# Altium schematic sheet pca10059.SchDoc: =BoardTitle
size A4; Organization: Nordic Semiconductor; SheetNumber: 1; SheetTotal: 1; CompanyName: Nordic Semiconductor; DocumentSize: A4
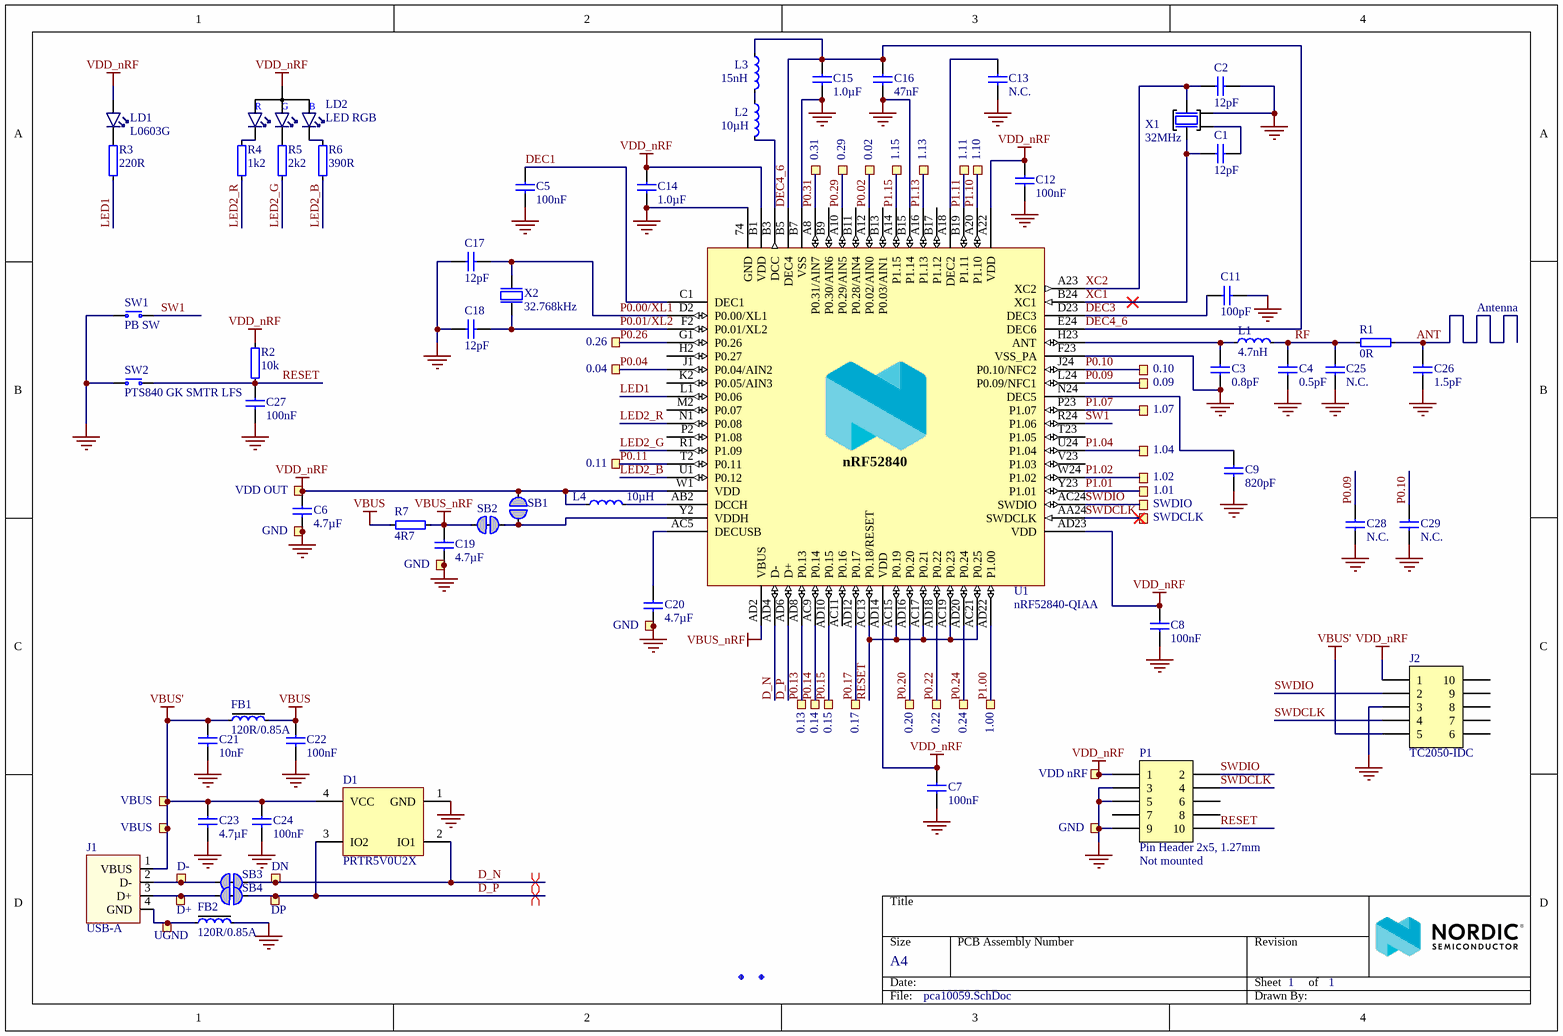
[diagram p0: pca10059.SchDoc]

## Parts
0.02  CH  [Castellated_Hole_0.9mm]  (value not drawn)  (no BOM)
0.04  Ø1.0mm,SMD  [TP_SMD_D1.0mm]  (value not drawn)  (no BOM)
0.09  CH  [Castellated_Hole_0.9mm]  (value not drawn)  (no BOM)
0.10  CH  [Castellated_Hole_0.9mm]  (value not drawn)  (no BOM)
0.11  Ø1.0mm,SMD  [TP_SMD_D1.0mm]  (value not drawn)  (no BOM)
0.13  CH  [Castellated_Hole_0.9mm]  (value not drawn)  (no BOM)
0.14  Ø1.0mm,SMD  [TP_SMD_D1.0mm]  (value not drawn)  (no BOM)
0.15  CH  [Castellated_Hole_0.9mm]  (value not drawn)  (no BOM)
0.17  CH  [Castellated_Hole_0.9mm]  (value not drawn)  (no BOM)
0.20  CH  [Castellated_Hole_0.9mm]  (value not drawn)  (no BOM)
0.22  CH  [Castellated_Hole_0.9mm]  (value not drawn)  (no BOM)
0.24  CH  [Castellated_Hole_0.9mm]  (value not drawn)  (no BOM)
0.26  Ø1.0mm,SMD  [TP_SMD_D1.0mm]  (value not drawn)  (no BOM)
0.29  CH  [Castellated_Hole_0.9mm]  (value not drawn)  (no BOM)
0.31  CH  [Castellated_Hole_0.9mm]  (value not drawn)  (no BOM)
1.00  CH  [Castellated_Hole_0.9mm]  (value not drawn)  (no BOM)
1.01  Ø1.0mm,SMD  [TP_SMD_D1.0mm]  (value not drawn)  (no BOM)
1.02  Ø1.0mm,SMD  [TP_SMD_D1.0mm]  (value not drawn)  (no BOM)
1.04  Ø1.0mm,SMD  [TP_SMD_D1.0mm]  (value not drawn)  (no BOM)
1.07  Ø1.0mm,SMD  [TP_SMD_D1.0mm]  (value not drawn)  (no BOM)
1.10  CH  [Castellated_Hole_0.9mm]  (value not drawn)  (no BOM)
1.11  Ø1.0mm,SMD  [TP_SMD_D1.0mm]  (value not drawn)  (no BOM)
1.13  CH  [Castellated_Hole_0.9mm]  (value not drawn)  (no BOM)
1.15  CH  [Castellated_Hole_0.9mm]  (value not drawn)  (no BOM)
C1  12pF  [CAPC0603X03L_C]
C2  12pF  [CAPC0603X03L_C]
C3  0.8pF  [CAPC0603X03L_C]
C4  0.5pF  [CAPC0603X03L_C]
C5  100nF  [CAPC0603X03L_C]
C6  4.7µF  [CAPC1608X06L]
C7  100nF  [CAPC0603X03L_C]
C8  100nF  [CAPC0603X03L_C]
C9  820pF  [CAPC0603X03L_C]
C11  100pF  [CAPC0603X03L_C]
C12  100nF  [CAPC0603X03L_C]
C13  N.C.  [CAPC0603X03L_C_NC]
C14  1.0µF  [CAPC1608X06L]
C15  1.0µF  [CAPC1608X06L]
C16  47nF  [CAPC0603X03L_C]
C17  12pF  [CAPC0603X03L_C]
C18  12pF  [CAPC0603X03L_C]
C19  4.7µF  [CAPC1005X04L]
C20  4.7µF  [CAPC1608X06L]
C21  10nF  [CAPC0603X03L_C]
C22  100nF  [CAPC0603X03L_C]
C23  4.7µF  [CAPC1005X04L]
C24  100nF  [CAPC0603X03L_C]
C25  N.C.  [CAPC0603X03L_C_NC]
C26  1.5pF  [CAPC0603X03L_C]
C27  100nF  [CAPC0603X03L_C]
C28  N.C.  [CAPC1005X04L_NC]
C29  N.C.  [CAPC1005X04L_NC]
D1  PRTR5V0U2X  [SOT190P230X110-4L]
D+  Ø1.0mm,SMD  [TP_SMD_D1.0mm]  (value not drawn)  (no BOM)
D-  Ø1.0mm,SMD  [TP_SMD_D1.0mm]  (value not drawn)  (no BOM)
DN  Ø1.0mm,SMD  [TP_SMD_D1.0mm]  (value not drawn)  (no BOM)
DP  Ø1.0mm,SMD  [TP_SMD_D1.0mm]  (value not drawn)  (no BOM)
FB1  120R/0.85A  [INDC0603X03L_C]
FB2  120R/0.85A  [INDC0603X03L_C]
Fid1  Fiducial mark  [Fiducial_Square]  (value not drawn)
Fid2  Fiducial mark  [Fiducial]  (value not drawn)
GND1  GND  [Castellated_Hole_0.9mm]  (no BOM)
GND2  GND  [Castellated_Hole_0.9mm_S]  (no BOM)
GND3  GND  [Castellated_Hole_0.9mm_S]  (no BOM)
GND4  GND  [TP_SMD_D1.0mm]  (no BOM)
J1  USB-A  [USB-A-PCB]  (no BOM)
J2  TC2050-IDC  [TC2050-IDC-NLFP]  (no BOM)
L1  4.7nH  [INDC0603X03L_C]
L2  10µH  [INDC1608X06L]
L3  15nH  [INDC1005X04L]
L4  10µH  [INDC1608X06L]
LD1  L0603G  [LED_0603_G]
LD2  LED RGB  [LED_RGB_0603]
P1  Pin Header 2x5, 1.27mm  Assembly: Not mounted  [HDR_2x5-SMD-1.27mm-NC]
R1  0R  [RESC0603X03L_C]
R2  10k  [RESC0603X03L_C]
R3  220R  [RESC0603X03L_C]
R4  1k2  [RESC0603X03L_C]
R5  2k2  [RESC0603X03L_C]
R6  390R  [RESC0603X03L_C]
R7  4R7  [RESC0603X03L_C]
SB1  Solderbridge  [Solderbridge]  (value not drawn)  (no BOM)
SB2  Solderbridge  [Solderbridge_Shorted]  (value not drawn)  (net tie, no BOM)
SB3  Solderbridge  [Solderbridge_Shorted]  (value not drawn)  (net tie, no BOM)
SB4  Solderbridge  [Solderbridge_Shorted]  (value not drawn)  (net tie, no BOM)
SW1  PB SW  [C&K_PTS810]
SW2  PTS840 GK SMTR LFS  [EVQP7A_J_B_K]
SWDCLK  CH  [Castellated_Hole_0.9mm_D]  (value not drawn)  (no BOM)
SWDIO  CH  [Castellated_Hole_0.9mm_D]  (value not drawn)  (no BOM)
U1  nRF52840-QIAA  [AQFN50P700X700X85_HS-74N]
UGND  Ø1.0mm,SMD  [TP_SMD_D1.0mm]  (value not drawn)  (no BOM)
VBUS1  VBUS  [Castellated_Hole_0.9mm]  (no BOM)
VBUS2  VBUS  [TP_SMD_D1.0mm]  (no BOM)
VDD_nRF  Ø1.0mm,SMD  [TP_SMD_D1.0mm]  (value not drawn)  (no BOM)
VDD_OUT  CH  [Castellated_Hole_0.9mm]  (value not drawn)  (no BOM)
X1  32MHz  [BT-XTAL_2016]
X2  32.768kHz  [XTAL_2012]

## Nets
GND: C2.2 C3.1 C4.1 C5.2 C6.2 C7.2 C8.2 C9.2 C11.2 C12.2 C13.2 C14.2 C15.1 C16.2 C17.2 C18.2 C19.2 C20.2 C21.1 C22.1 C23.1 C24.1 C25.2 C26.1 C27.1 C28.1 C29.2 D1.1(GND) FB2.2 GND1.1 GND2.1 GND3.1 GND4.1 J2.3 P1.3 P1.5 P1.9 SW1.2(COM) SW2.2(COM) U1.74(GND) U1.B7(VSS) U1.B15(P1.14) U1.F23(VSS_PA) X1.2(GND)
VBUS: C22.2 FB1.2 R7.2
VBUS': C21.2 C23.2 C24.2 D1.4(VCC) FB1.1 J1.1(VBUS) J2.5 VBUS1.1 VBUS2.1
VBUS_nRF: C19.1 R7.1 SB2.2 U1.AD2(VBUS)
VDD_nRF: C6.1 C7.1 C8.1 C12.1 C14.1 J2.1 L4.1 LD1.2(A) LD2.4(A) P1.1 R2.2 SB1.1 U1.A22(VDD) U1.AD14(VDD) U1.AD23(VDD) U1.B1(VDD) U1.W1(VDD) VDD_nRF.1 VDD_OUT.1
ANT: C26.2 R1.2
D_N: D1.2(IO1) DN.1 SB3.1 U1.AD4(D-)
D_P: D1.3(IO2) DP.1 SB4.1 U1.AD6(D+)
DEC1: C5.1 U1.C1(DEC1)
DEC3: C11.1 U1.D23(DEC3)
DEC4_6: C15.2 C16.1 L3.1 U1.B5(DEC4) U1.E24(DEC6)
LED1: R3.1 U1.L1(P0.06)
LED2_B: R6.1 U1.U1(P0.12)
LED2_G: R5.1 U1.R1(P1.09)
LED2_R: R4.1 U1.N1(P0.08)
P0.00/XL1: C17.1 U1.D2(P0.00/XL1) X2.1(inp)
P0.01/XL2: C18.1 U1.F2(P0.01/XL2) X2.2(out)
P0.02: 0.02.1 U1.A12(P0.02/AIN0)
P0.04: 0.04.1 U1.J1(P0.04/AIN2)
P0.09: 0.09.1 C28.2 U1.L24(P0.09/NFC1)
P0.10: 0.10.1 C29.1 U1.J24(P0.10/NFC2)
P0.11: 0.11.1 U1.T2(P0.11)
P0.13: 0.13.1 U1.AD8(P0.13)
P0.14: 0.14.1 U1.AC9(P0.14)
P0.15: 0.15.1 U1.AD10(P0.15)
P0.17: 0.17.1 U1.AD12(P0.17)
P0.20: 0.20.1 U1.AD16(P0.20)
P0.22: 0.22.1 U1.AD18(P0.22)
P0.24: 0.24.1 U1.AD20(P0.24)
P0.26: 0.26.1 U1.G1(P0.26)
P0.29: 0.29.1 U1.A10(P0.29/AIN5)
P0.31: 0.31.1 U1.A8(P0.31/AIN7)
P1.00: 1.00.1 U1.AD22(P1.00)
P1.01: 1.01.1 U1.Y23(P1.01)
P1.02: 1.02.1 U1.W24(P1.02)
P1.04: 1.04.1 U1.U24(P1.04)
P1.07: 1.07.1 U1.P23(P1.07)
P1.10: 1.10.1 U1.A20(P1.10)
P1.11: 1.11.1 U1.B19(P1.11)
P1.13: 1.13.1 U1.A16(P1.13)
P1.15: 1.15.1 U1.A14(P1.15)
RESET: C27.2 P1.10 R2.1 SW2.1(N.O) U1.AC13(P0.18/RESET) U1.AC15(P0.19) U1.AC17(P0.21) U1.AC19(P0.23) U1.AC21(P0.25)
RF: C4.2 C25.1 L1.2 R1.1
SW1: SW1.1(N.O) U1.R24(P1.06)
SWDCLK: J2.4 P1.4 SWDCLK.1 U1.AA24(SWDCLK)
SWDIO: J2.2 P1.2 SWDIO.1 U1.AC24(SWDIO)
XC1: C1.1 U1.B24(XC1) X1.1(IN)
XC2: C2.1 U1.A23(XC2) X1.3(OUT)
NetC1_2: C1.2 X1.4(GND)
NetC3_2: C3.2 L1.1 U1.H23(ANT)
NetC9_1: C9.1 U1.N24(DEC5)
NetC13_1: C13.1 U1.A18(DEC2)
NetC20_1: C20.1 U1.AC5(DECUSB)
NetD+_1: D+.1 J1.3(D+) SB4.2
NetD-_1: D-.1 J1.2(D-) SB3.2
NetFB2_1: FB2.1 J1.4(GND) UGND.1
NetL2_1: L2.1 L3.2
NetL2_2: L2.2 U1.B3(DCC)
NetL4_2: L4.2 U1.AB2(DCCH)
NetLD1_1: LD1.1(C) R3.2
NetLD2_1: LD2.1(C_RED) R4.2
NetLD2_2: LD2.2(C_GREEN) R5.2
NetLD2_3: LD2.3(C_BLUE) R6.2
NetSB1_2: SB1.2 SB2.1 U1.Y2(VDDH)

Not connected (* = marked no-connect by the designer): J2 6 7 8 9 10; P1 6 7 8; U1 AC11(P0.16) B9(P0.30/AIN6) B11(P0.28/AIN4) B13(P0.03/AIN1) B17(P1.12) H2(P0.27) K2(P0.05/AIN3) M2(P0.07) P2(P1.08) T23(P1.05) V23(P1.03)

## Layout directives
differential pair: D_N, D_P

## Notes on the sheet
- Antenna

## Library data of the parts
0.02 0.09 0.10 0.13 0.15 0.17 0.20 0.22 0.24 0.29 0.31 1.00 1.10 1.13 1.15 GND1 VBUS1 VDD_OUT = Castellated Hole 0.9mm: Manufacturer: N.A.; Pad Count: 1
0.04 0.11 0.14 0.26 1.01 1.02 1.04 1.07 1.11 D+ D- DN DP GND4 UGND VBUS2 VDD_nRF = TP_SMD_Ø1.0MM: 1.0mm circular SMD testpad; Manufacturer: Nordic Semiconductor; Manufacturer Part Number: N.A.; Pad Count: 1
C1 C2 C17 C18 = C0201-12p: Capacitor, NP0, ±2%; Manufacturer: N.A.; Part number IPS: 00000007848; Note: 25V; Pad Count: 2
C3 = C0201-0.8p: Capacitor, NP0, ±0.05pF, 50V; Manufacturer: Murata; Manufacturer Part Number: GJM0335C1HR80WB01; Part number IPS: 80000001975; Artikkelnr Noca: N.A.; Pad Count: 2
C4 = C0201-0.5p: Capacitor, NP0, ±0.05pF; Manufacturer: N.A.; Note: 50V; Pad Count: 2
C5 C7 C8 C12 C22 C24 C27 = C0201-100n: Capacitor, X5R, ±10%; Manufacturer: N.A.; Part number IPS: 00000001248, 00000002505; Note: 16V; Pad Count: 2
C6 C20 = C0603-4µ7: Capacitor, X5R, ±10%; Manufacturer: N.A.; Part number IPS: 00000007783; Note: 6.3V; Artikkelnr Noca: 20069060; Pad Count: 2
C9 = C0201-820p: Capacitor, X7R, ±10%; Manufacturer: N.A.; Part number IPS: 00000001249; Note: 25V; Pad Count: 2
C11 = C0201-100p: Capacitor, NP0, ±2%, 25V; Manufacturer: Murata; Manufacturer Part Number: GRM0335C1E101GA01; Part number IPS: 00000007853; Artikkelnr Noca: N.A.; Pad Count: 2
C13 C25 = C0201-N.C.: Not mounted; Manufacturer: N.A.; Note: Chip Cap; Assembly: Not mounted; Pad Count: 2
C14 C15 = C0603-1µ0: Capacitor, X7R, ±10%; Manufacturer: N.A.; Part number IPS: 00000000616; Note: 16V; Artikkelnr Noca: 20039282; Pad Count: 2
C16 = C0201-47n: Capacitor, X5R, ±10%; Manufacturer: N.A.; Part number IPS: 00000001250; Note: 10V; Pad Count: 2
C19 C23 = C0402-4µ7: Capacitor, X5R, ±20%; Manufacturer: N.A.; Part number IPS: 00000001251, 00000007165; Note: 10V; Artikkelnr Noca: 20039482; Pad Count: 2
C21 = C0201-10n: Capacitor, X7R, ±10%; Manufacturer: N.A.; Part number IPS: 00000003480; Note: 10V; Pad Count: 2
C26 = C0201-1.5p: Capacitor, NP0, ±0.1pF; Manufacturer: N.A.; Part number IPS: 00000007107; Note: 50V; Pad Count: 2
C28 C29 = C0402-N.C.: Not mounted; Manufacturer: N.A.; Assembly: Not mounted; Note: Chip Cap; Pad Count: 2
D1 = PRTR5V0U2X: Ultra low capacitance double rail-to-rail ESD protection diode; Manufacturer: NXP Semiconductors; Part number IPS: 00000009951; Note: N.A.; Artikkelnr Noca: 10069015; Pad Count: 4
FB1 FB2 = FB0201-120R@100M-850mA: Ferrite Bead, 120 Ohm @ 100MHz, 850mA, 150 mOhm Max; Manufacturer: Taiyo Yuden; Manufacturer Part Number: BKP0603HS121-T; Part number IPS: 00000001252; Note: Chip EMIFIL Inductor Type Chip Ferrite Bead; Artikkelnr Noca: N.A.; Pad Count: 2
Fid1 = Fid-Mark-Square: Manufacturer: N.A.; Value: N.A.; Pad Count: 1
Fid2 = Fid-Mark: Manufacturer: N.A.; Value: N.A.; Pad Count: 1
GND2 GND3 = Castellated Hole 0.9mm_S: Castellated Hole 0.9mm; Manufacturer: N.A.; Pad Count: 1
J1 = USB-A-PCB: USB-A PCB footprint; Manufacturer: N.A.; Pad Count: 4
J2 = TC2050-IDC-NLFP: CBL PLUG-OF-NAILS 10-PIN; Manufacturer: Tag-Connect LLC; Artikkelnr Noca: N.A.; Pad Count: 10
L1 = L0201-4n7: Inductor, 350mA, ±3%; Manufacturer: Murata; Manufacturer Part Number: LQP03TN4N7H02D; Part number IPS: 00000001792; Note: N.A.; Pad Count: 2
L2 L4 = L0603-10µ: Inductor, 80mA, ±10%; Manufacturer: Taiyo Yuden; Manufacturer Part Number: LBMF1608T100K; Part number IPS: 00000007794; Part number Norautron: N.A.; Note: LBMF1608T100K 10µH 80mA 0603; Artikkelnr Noca: 33029314; Pad Count: 2
L3 = L0402-15n: Inductor, 320mA, ±5%; Manufacturer: Taiyo Yuden; Manufacturer Part Number: HK100515NJ-T; Part number IPS: 00000001262; Part number Norautron: N.A.; Note: High frequency chip inductor ±10%; Artikkelnr Noca: 33029323; Pad Count: 2
LD1 = VS 25C7M5: LED, Green, 0603, 573nm, Vf=2.0V, 24mcd, - 40 to +85°C; Manufacturer: Victory Electronics; Part number IPS: 00000001274, 00000009961; Note: N.A.; Artikkelnr Noca: 13019193; Pad Count: 2
LD2 = APHF1608LSEEQBDZGKC: RGB LED 1.60 mm x 0.80 mm SMD; Manufacturer: Kingbright Company LLC; Part number IPS: 00000001254; Note: N.A.; Pad Count: 4
P1 = Pin Header 2x5 SMD, 1.27mm, KS, N.C.: Pin Header 2x5, 1.27mm (50mil), SMD, Keying Shroud; Manufacturer: W-CON; Manufacturer Part Number: 3132-10MS0BK00R1; Note: N.A.; Pad Count: 10
R1 = R0201-0R: Resistor, ±5%, 0.05W; Manufacturer: N.A.; Part number IPS: 00000003245; Note: Chip Res 5%; Pad Count: 2
R2 = R0201-10k: Resistor, ±1%, 0.05W; Manufacturer: N.A.; Part number IPS: 00000001255; Note: Chip Res 1%; Pad Count: 2
R3 = R0201-220: Resistor, ±1%, 0.05W; Manufacturer: N.A.; Part number IPS: 00000000863; Note: Chip Res 1%; Pad Count: 2
R4 = R0201-1k2: Resistor, ±1%, 0.05W; Manufacturer: N.A.; Part number IPS: 00000001256; Note: Chip Res 1%; Pad Count: 2
R5 = R0201-2k2: Resistor, ±1%, 0.05W; Manufacturer: N.A.; Part number IPS: 00000001257; Note: Chip Res 1%; Pad Count: 2
R6 = R0201-390: Resistor, ±1%, 0.05W; Manufacturer: N.A.; Part number IPS: 00000001258; Note: Chip Res 1%; Pad Count: 2
R7 = R0201-4R7: Resistor, ±1%, 0.05W; Manufacturer: N.A.; Part number IPS: 00000002486; Note: Chip Res 1%; Pad Count: 2
SB1 = Solderbridge: Manufacturer: N.A.; Pad Count: 2
SB2-SB4 = Solderbridge Shorted: Shorted Solderbridge; Manufacturer: N.A.; Pad Count: 2
SW1 = PTS810 SJK 250 SMTR LFS: Tactile Switch, SPNO, SMD, 260gf, 4.2x3.2x2.5mm; Manufacturer: C&K; Part number IPS: 00000001259; Note: N.A.; Pad Count: 4
SW2 = PTS840 GK SMTR LFS: Microminiature SMT Switch, Side Actuated; Manufacturer: C&K; Part number IPS: 00000001260; Part number Norautron: N.A.; Note: Tactile Switch, SPST, SMD, 220gf; Artikkelnr Noca: 50019089; Pad Count: 4
SWDCLK SWDIO = Castellated Hole 0.9mm_D: Castellated Hole 0.9mm; Manufacturer: N.A.; Pad Count: 1
U1 = nRF52840-QIAAF0: Multi-protocol Bluetooth Low Energy, IEEE 802.15.4, ANT and 2.4GHz proprietary system-on-chip; Manufacturer: Nordic Semiconductor; Note: N.A.; Pad Count: 73
X1 = XTAL_SMD2016_32MHz_8pF_Murata: XTAL SMD 2016, 32MHz, Cl=8pF, Tol: ±10ppm, Stab: ±10ppm; Manufacturer: Murata; Manufacturer Part Number: XRCGB32M000F1H01R0; Part number IPS: 80000001424; Note: XTAL SMD 32.000MHz; Artikkelnr Noca: N.A.; Pad Count: 4
X2 = XTAL_SMD2012_32.768kHz_9pF_Seiko: XTAL SMD 2012, 32.768kHz, 9pF, ±20ppm; Manufacturer: Seiko Instruments; Manufacturer Part Number: SC20S-9.0PF20PPM; Part number IPS: 80000001425; Note: XTAL SMD 32.768kHz; Artikkelnr Noca: N.A.; Pad Count: 2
